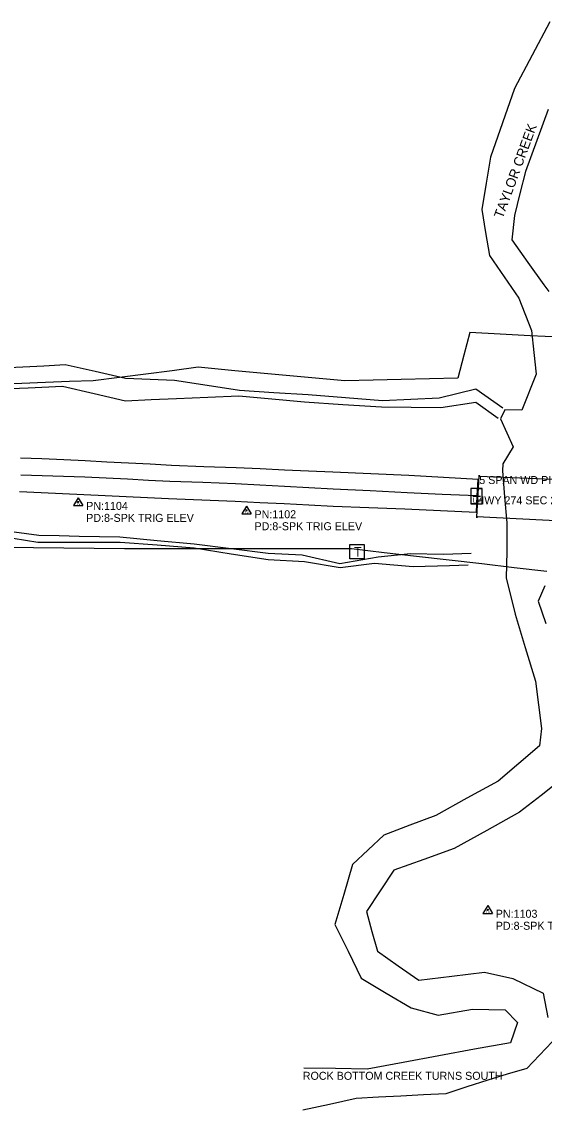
# Model space of a CAD drawing. Extents: x 1138803 to 1169983, y 1655906 to 1658226.
# Drawn here: x 1164595 to 1164922, y 1656363 to 1657043 of the extents above; entities that cross this region are included whole.
import ezdxf

# ---------------------------------------------------------------- set-up
doc = ezdxf.new("R2010")
doc.units = 0
for name, color, linetype in [('R_Annotation', 7, 'Continuous'), ('S_BRIDGE', 7, 'Continuous'), ('S_BRIDGE_ANNOT', 7, 'Continuous'), ('S_DITCHLINE', 7, 'Continuous'), ('S_EDGE_PAVEMENT', 7, 'Continuous'), ('S_LOG_MILE', 7, 'Continuous'), ('S_LOG_MILE_ANNOT', 7, 'Continuous'), ('S_MSC_PT_SYM', 7, 'Continuous'), ('S_PAVEMENT_CROWN', 7, 'Continuous'), ('S_SECONDARY_CTL', 7, 'Continuous'), ('S_SECONDARY_CTL_ANNOT', 7, 'Continuous'), ('S_STR_PT_SYM', 7, 'Continuous'), ('S_STREAM', 7, 'Continuous'), ('S_SURVEY_TEXT_ANNOT', 7, 'Continuous'), ('S_TELEPHONE_UTILITIES', 7, 'Continuous'), ('S_TREE', 7, 'Continuous')]:
    doc.layers.add(name, color=color, linetype=linetype)

msp = doc.modelspace()

# ---------------------------------------------------------------- linework, layer by layer
at = {"layer": 'S_BRIDGE'}
for p, q in [((1164879.69, 1656733.51), (1164881.2, 1656759.11)), ((1164881.2, 1656759.11), (1164957.76, 1656755.87)), ((1164956.58, 1656729.86), (1164879.69, 1656733.51))]:
    msp.add_line(p, q, dxfattribs=at)
at = {"layer": 'S_DITCHLINE'}
for points in [[(1164896.02, 1656801.5), (1164878.98, 1656813.41), (1164856.12, 1656807.69), (1164838.47, 1656806.85), (1164820.82, 1656806), (1164797.54, 1656807.95), (1164774.26, 1656809.89), (1164752.83, 1656811.17), (1164731.39, 1656812.45), (1164711.13, 1656815.59), (1164690.87, 1656818.73), (1164675.52, 1656819.43), (1164660.16, 1656820.13), (1164641.34, 1656824.34), (1164622.52, 1656828.55), (1164609.26, 1656827.85), (1164596.01, 1656827.16), (1164582.75, 1656826.46)], [(1164893.06, 1656794.96), (1164879.02, 1656805.04), (1164857.12, 1656801.67), (1164838.58, 1656801.87), (1164820.05, 1656802.07), (1164796.06, 1656803.64), (1164772.06, 1656805.22), (1164751.54, 1656807.12), (1164731.02, 1656809.03), (1164711.53, 1656808.17), (1164692.04, 1656807.32), (1164676.17, 1656806.65), (1164660.3, 1656805.98), (1164640.56, 1656810.49), (1164620.81, 1656815), (1164599.31, 1656814.04), (1164577.81, 1656813.08)], [(1164876.18, 1656710.75), (1164858.78, 1656710.1), (1164838.21, 1656710.43), (1164818.13, 1656708.33), (1164794.09, 1656704.25), (1164770.65, 1656709.7), (1164749.4, 1656710.78), (1164726.22, 1656713.68), (1164703.05, 1656716.58), (1164679.9, 1656718.7), (1164656.74, 1656720.83), (1164644.05, 1656721.11), (1164631.35, 1656721.4), (1164618.66, 1656721.69), (1164605.97, 1656721.98), (1164583.02, 1656725.15)], [(1164874.3, 1656703.42), (1164862.68, 1656703.05), (1164839.9, 1656702.34), (1164815.65, 1656704.53), (1164794.33, 1656701.75), (1164772.01, 1656705.51), (1164749.36, 1656706.72), (1164726.27, 1656710.35), (1164703.19, 1656713.97), (1164680.02, 1656715.81), (1164656.84, 1656717.66), (1164644.02, 1656717.65), (1164631.19, 1656717.65), (1164618.36, 1656717.64), (1164605.53, 1656717.64), (1164582.38, 1656721.3)]]:
    msp.add_lwpolyline(points, dxfattribs=at)
at = {"layer": 'S_EDGE_PAVEMENT'}
for points in [[(1164880.41, 1656756.92), (1164858.77, 1656758.13), (1164837.13, 1656759.34), (1164813.41, 1656760.43), (1164789.68, 1656761.52), (1164774.58, 1656762.18), (1164759.48, 1656762.84), (1164744.38, 1656763.5), (1164729.28, 1656764.16), (1164709.14, 1656764.95), (1164689, 1656765.74), (1164675.52, 1656766.44), (1164662.05, 1656767.15), (1164648.58, 1656767.85), (1164635.1, 1656768.56), (1164621.57, 1656769.15), (1164608.03, 1656769.75), (1164594.5, 1656770.34)], [(1164880.33, 1656756.92), (1164879.65, 1656746.66), (1164879.16, 1656736.25), (1164856.88, 1656737.34), (1164834.61, 1656738.43), (1164812.27, 1656739.26), (1164789.94, 1656740.1), (1164774.64, 1656740.87), (1164759.35, 1656741.64), (1164744.05, 1656742.42), (1164728.76, 1656743.19), (1164707.91, 1656744.02), (1164687.05, 1656744.85), (1164673.85, 1656745.47), (1164660.64, 1656746.09), (1164647.43, 1656746.71), (1164634.22, 1656747.33), (1164620.82, 1656747.93), (1164607.41, 1656748.54), (1164594, 1656749.15)]]:
    msp.add_lwpolyline(points, dxfattribs=at)
at = {"layer": 'S_LOG_MILE'}
for p, q in [((1164877.1, 1656746.43), (1164881.9, 1656746.43)), ((1164879.5, 1656751.23), (1164883.1, 1656751.23)), ((1164879.5, 1656741.63), (1164875.9, 1656741.63))]:
    msp.add_line(p, q, dxfattribs=at)
msp.add_lwpolyline([(1164883.1, 1656751.23), (1164875.9, 1656751.23), (1164875.9, 1656741.63), (1164883.1, 1656741.63)], close=True, dxfattribs=at)
at = {"layer": 'S_MSC_PT_SYM'}
msp.add_lwpolyline([(1164770.96, 1656386.82), (1164770.96, 1656386.87), (1164770.96, 1656386.82), (1164770.91, 1656386.82), (1164770.96, 1656386.82), (1164770.96, 1656386.77), (1164770.96, 1656386.82), (1164771.01, 1656386.82)], dxfattribs=at)
at = {"layer": 'S_PAVEMENT_CROWN'}
msp.add_lwpolyline([(1164879.65, 1656746.66), (1164857.94, 1656747.65), (1164836.23, 1656748.63), (1164813.07, 1656749.78), (1164789.91, 1656750.94), (1164774.67, 1656751.77), (1164759.43, 1656752.59), (1164744.19, 1656753.42), (1164728.95, 1656754.24), (1164708.44, 1656754.98), (1164687.93, 1656755.71), (1164674.66, 1656756.4), (1164661.38, 1656757.09), (1164648.11, 1656757.78), (1164634.83, 1656758.48), (1164621.49, 1656758.9), (1164608.14, 1656759.32), (1164594.8, 1656759.74)], dxfattribs=at)
at = {"layer": 'S_SECONDARY_CTL'}
for p, q in [((1164630.64, 1656745.57), (1164627.63, 1656740.61)), ((1164630.64, 1656745.57), (1164633.58, 1656740.61)), ((1164627.63, 1656740.61), (1164633.58, 1656740.61)), ((1164735.78, 1656740.34), (1164732.77, 1656735.39)), ((1164735.78, 1656740.34), (1164738.73, 1656735.39)), ((1164732.77, 1656735.39), (1164738.73, 1656735.39)), ((1164886.5, 1656490.68), (1164883.49, 1656485.73)), ((1164886.5, 1656490.68), (1164889.45, 1656485.73)), ((1164883.49, 1656485.73), (1164889.45, 1656485.73))]:
    msp.add_line(p, q, dxfattribs=at)
for centre, radius in [((1164630.64, 1656742.96), 0.311), ((1164630.64, 1656742.96), 0.183), ((1164630.64, 1656742.96), 0.103), ((1164735.78, 1656737.73), 0.311), ((1164735.78, 1656737.73), 0.183), ((1164735.78, 1656737.73), 0.103), ((1164886.5, 1656488.07), 0.311), ((1164886.5, 1656488.07), 0.183), ((1164886.5, 1656488.07), 0.103)]:
    msp.add_circle(centre, radius, dxfattribs=at)
at = {"layer": 'S_STR_PT_SYM'}
for points in [[(1164881.2, 1656759.11), (1164881.2, 1656759.61), (1164881.2, 1656759.11), (1164880.7, 1656759.11), (1164881.2, 1656759.11), (1164881.2, 1656758.61), (1164881.2, 1656759.11), (1164881.7, 1656759.11)], [(1164879.69, 1656733.51), (1164879.69, 1656734.01), (1164879.69, 1656733.51), (1164879.19, 1656733.51), (1164879.69, 1656733.51), (1164879.69, 1656733.01), (1164879.69, 1656733.51), (1164880.19, 1656733.51)]]:
    msp.add_lwpolyline(points, dxfattribs=at)
at = {"layer": 'S_STREAM'}
for points in [[(1164925.26, 1657042.97), (1164914.27, 1657022.13), (1164903.28, 1657001.29), (1164895.77, 1656979.8), (1164888.27, 1656958.32), (1164885.52, 1656942.01), (1164882.77, 1656925.69), (1164885.18, 1656911.31), (1164887.59, 1656896.92), (1164896.73, 1656883.56), (1164905.86, 1656870.19), (1164913.84, 1656850.03), (1164915.27, 1656836.35), (1164916.7, 1656822.68), (1164907.82, 1656800.25), (1164897.09, 1656800.4), (1164894.44, 1656794.83), (1164902.3, 1656777.41), (1164895.93, 1656766.63), (1164895.63, 1656762.38), (1164897.05, 1656746.16), (1164898.46, 1656729.94), (1164898.41, 1656711.9), (1164897.95, 1656695.5), (1164903.53, 1656672.85), (1164909.97, 1656651.88), (1164916.41, 1656630.92), (1164918.28, 1656616.17), (1164920.15, 1656601.42), (1164918.79, 1656590.54), (1164905.9, 1656579.48), (1164893, 1656568.41), (1164873.53, 1656557.74), (1164854.07, 1656547.07), (1164837.83, 1656540.91), (1164821.59, 1656534.76), (1164811.84, 1656525.53), (1164802.1, 1656516.3), (1164796.5, 1656497.62), (1164790.9, 1656478.95), (1164799.2, 1656462.14), (1164807.5, 1656445.34), (1164823.1, 1656436.04), (1164838.7, 1656426.73), (1164855.48, 1656422.23), (1164876.98, 1656425.9), (1164897.4, 1656425.47), (1164905.09, 1656417.59), (1164900.68, 1656404.98), (1164878.32, 1656400.86), (1164855.96, 1656396.73), (1164833.6, 1656392.61), (1164811.24, 1656388.49), (1164791.4, 1656388.84), (1164771.57, 1656389.18)], [(1164924.33, 1656988.25), (1164917.16, 1656968.82), (1164909.99, 1656949.4), (1164906.58, 1656935.66), (1164903.17, 1656921.92), (1164901.64, 1656906.66), (1164911.6, 1656892.61), (1164921.55, 1656878.57), (1164924.67, 1656874.35)], [(1164922.07, 1656690.39), (1164917.94, 1656681), (1164922.87, 1656666.92)], [(1164933.27, 1656570.12), (1164919.81, 1656559.57), (1164906.35, 1656549.02), (1164885.92, 1656537.66), (1164865.49, 1656526.3), (1164846.61, 1656519.52), (1164827.73, 1656512.74), (1164819.24, 1656499.82), (1164810.75, 1656486.9), (1164814.17, 1656474.53), (1164817.59, 1656462.16), (1164830.57, 1656453.11), (1164843.54, 1656444.05), (1164864.06, 1656446.54), (1164884.57, 1656449.03), (1164902.1, 1656445.04), (1164921.04, 1656435.95), (1164923.93, 1656420.7)], [(1164926.83, 1656405.44), (1164910.85, 1656388.88), (1164898.68, 1656385.25), (1164886.51, 1656381.62), (1164873.4, 1656377.34), (1164860.29, 1656373.06), (1164846.28, 1656372.33), (1164832.28, 1656371.61), (1164818.27, 1656370.89), (1164804.27, 1656370.16), (1164787.64, 1656366.48), (1164771.02, 1656362.8)]]:
    msp.add_lwpolyline(points, dxfattribs=at)
at = {"layer": 'S_TELEPHONE_UTILITIES'}
msp.add_lwpolyline([(1164800.34, 1656707.31), (1164800.34, 1656716.31), (1164809.34, 1656716.31), (1164809.34, 1656707.31)], close=True, dxfattribs=at)
at = {"layer": 'S_TREE'}
for points in [[(1164931.83, 1656845.81), (1164913.02, 1656846.78), (1164894.2, 1656847.75), (1164875.38, 1656848.72), (1164871.56, 1656834.54), (1164867.73, 1656820.36), (1164850.12, 1656819.91), (1164832.51, 1656819.47), (1164814.9, 1656819.03), (1164797.3, 1656818.58), (1164774.39, 1656820.7), (1164751.49, 1656822.81), (1164728.58, 1656824.92), (1164705.68, 1656827.04), (1164689.28, 1656824.94), (1164672.89, 1656822.85), (1164656.49, 1656820.75), (1164640.09, 1656818.66), (1164625.2, 1656818.09), (1164610.3, 1656817.52), (1164595.41, 1656816.95), (1164580.51, 1656816.38)], [(1164923.43, 1656699.5), (1164903.09, 1656701.84), (1164882.75, 1656704.18), (1164862.42, 1656706.52), (1164842.08, 1656708.86), (1164821.75, 1656711.2), (1164801.41, 1656713.54), (1164783.68, 1656713.56), (1164765.95, 1656713.57), (1164748.22, 1656713.59), (1164730.48, 1656713.6), (1164712.75, 1656713.61), (1164695.02, 1656713.63), (1164677.28, 1656713.64), (1164659.55, 1656713.66), (1164640.61, 1656713.87), (1164621.67, 1656714.09), (1164602.73, 1656714.3), (1164583.79, 1656714.52)]]:
    msp.add_lwpolyline(points, dxfattribs=at)

# ---------------------------------------------------------------- texts
at = {"layer": 'R_Annotation'}
msp.add_text('TAYLOR CREEK', height=6, rotation=69.75273, dxfattribs=at).set_placement((1164895.83, 1656919.67))
at = {"layer": 'S_BRIDGE_ANNOT'}
msp.add_text('5 SPAN WD PILON WD DECK', height=5, dxfattribs=at).set_placement((1164881.2, 1656754.11))
at = {"layer": 'S_LOG_MILE'}
msp.add_text('LM', height=3, rotation=360, dxfattribs=at).set_placement((1164876.96, 1656742.59))
at = {"layer": 'S_LOG_MILE_ANNOT'}
msp.add_text('HWY 274 SEC 2 LM 16.11', height=5, dxfattribs=at).set_placement((1164879.5, 1656741.43))
at = {"layer": 'S_SECONDARY_CTL'}
for p in [(1164629.43, 1656740.95), (1164734.58, 1656735.72), (1164885.3, 1656486.06)]:
    msp.add_text('TV', height=1.5, rotation=360, dxfattribs=at).set_placement(p)
at = {"layer": 'S_SECONDARY_CTL_ANNOT'}
for s, p in [('PN:1104', (1164635.64, 1656737.96)), ('PD:8-SPK TRIG ELEV', (1164635.64, 1656730.46)), ('PN:1102', (1164740.78, 1656732.73)), ('PD:8-SPK TRIG ELEV', (1164740.78, 1656725.23)), ('PN:1103', (1164891.5, 1656483.07)), ('PD:8-SPK TRIG ELEV', (1164891.5, 1656475.57))]:
    msp.add_text(s, height=5, dxfattribs=at).set_placement(p)
at = {"layer": 'S_SURVEY_TEXT_ANNOT'}
msp.add_text('ROCK BOTTOM CREEK TURNS SOUTH', height=5, dxfattribs=at).set_placement((1164770.96, 1656381.82))
at = {"layer": 'S_TELEPHONE_UTILITIES'}
msp.add_text('T', height=6, rotation=360, dxfattribs=at).set_placement((1164802.9, 1656708.81))

doc.saveas('drawing.dxf')
